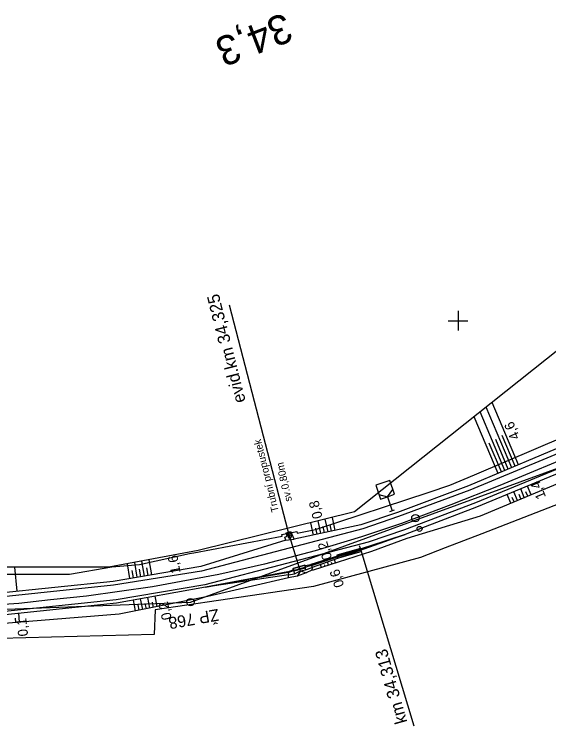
# Model space of a CAD drawing. Extents: x -805730 to -804640, y -1150889 to -1150366.
# Drawn here: x -805190.1 to -805081.6, y -1150682.3 to -1150537.8 of the extents above; entities that cross this region are included whole.
import ezdxf

# ---------------------------------------------------------------- set-up
doc = ezdxf.new("R2010")
doc.units = 0
for name, color, linetype in [('0381KM032-037P - Vrstva 1', 7, 'Continuous'), ('0381KM032-037P - Vrstva 13', 7, 'Continuous'), ('0381KM032-037P - Vrstva 17', 7, 'Continuous'), ('0381KM032-037P - Vrstva 19', 7, 'Continuous'), ('0381KM032-037P - Vrstva 4', 7, 'Continuous'), ('0381KM032-037P - Vrstva 48', 7, 'Continuous'), ('0381KM032-037P - Vrstva 49', 7, 'Continuous'), ('0381KM032-037P - Vrstva 7', 7, 'Continuous'), ('0381KM032-037P - Vrstva 9', 7, 'Continuous'), ('hran DP - hran DP', 7, 'Continuous'), ('krizky_1000 - Vrstva 1', 7, 'Continuous'), ('vyt_sit - polygon', 7, 'Continuous'), ('vyt_sit - stávající', 7, 'Continuous')]:
    doc.layers.add(name, color=color, linetype=linetype)

msp = doc.modelspace()

# ---------------------------------------------------------------- linework, layer by layer
at = {"layer": '0381KM032-037P - Vrstva 1'}
for points in [[(-805074.24, -1150626.27), (-805091.51, -1150633.48)], [(-805091.51, -1150633.48), (-805101.49, -1150637.38), (-805111.46, -1150641.17)], [(-805111.46, -1150641.17), (-805119.63, -1150643.91), (-805129.05, -1150646.75), (-805139.28, -1150649.43), (-805148.59, -1150651.52), (-805162.04, -1150654.03), (-805175.42, -1150655.94), (-805182.79, -1150656.72)], [(-805182.79, -1150656.72), (-805189.2, -1150657.4), (-805199.42, -1150658.12), (-805222.35, -1150659), (-805235.71, -1150659.34), (-805248.65, -1150659.92), (-805262.34, -1150660.99)]]:
    msp.add_lwpolyline(points, dxfattribs=at)
at = {"layer": '0381KM032-037P - Vrstva 13'}
for p, q in [((-805129.78, -1150649.7), (-805129.65, -1150650.12)), ((-805133.42, -1150650.74), (-805132.59, -1150650.52)), ((-805133.42, -1150650.74), (-805133.23, -1150651.44)), ((-805131.99, -1150650.77), (-805132.69, -1150651.85)), ((-805131.99, -1150650.77), (-805132.2, -1150650.41)), ((-805131.99, -1150650.77), (-805130.88, -1150651.21)), ((-805131, -1150650.07), (-805131.81, -1150650.3)), ((-805130.99, -1150650.58), (-805131, -1150650.07))]:
    msp.add_line(p, q, dxfattribs=at)
for points in [[(-805129.89, -1150649.51), (-805129.78, -1150649.7), (-805131, -1150650.07), (-805131, -1150650.07), (-805131.07, -1150649.74), (-805129.89, -1150649.51)], [(-805134.49, -1150651.14), (-805134.56, -1150650.98), (-805133.46, -1150650.58), (-805133.42, -1150650.74), (-805133.42, -1150650.74), (-805134.49, -1150651.14), (-805134.45, -1150651.61)], [(-805129.65, -1150650.12), (-805129.71, -1150650.67), (-805130.88, -1150651.21), (-805132.69, -1150651.85), (-805134.43, -1150652.2), (-805134.45, -1150651.61), (-805133.23, -1150651.44)], [(-805133.23, -1150651.44), (-805131.99, -1150650.77), (-805130.99, -1150650.58)], [(-805130.99, -1150650.58), (-805129.65, -1150650.12)]]:
    msp.add_lwpolyline(points, dxfattribs=at)
msp.add_ellipse((-805132.2, -1150650.41), major_axis=(-0.388, -0.106), ratio=0.004829, start_param=3.14712, end_param=6.275171, dxfattribs=at)
at = {"layer": '0381KM032-037P - Vrstva 17'}
msp.add_lwpolyline([(-805070.8, -1150598.9), (-805121.06, -1150638.84), (-805152.76, -1150646.7), (-805170.92, -1150650.08), (-805194.39, -1150650.05), (-805213.2, -1150651.26), (-805221.79, -1150652.33), (-805228.79, -1150654.03)], dxfattribs=at)
at = {"layer": '0381KM032-037P - Vrstva 19'}
for p, q in [((-805146.46, -1150596.75), (-805134.12, -1150644.47)), ((-805133.42, -1150650.74), (-805132.59, -1150650.52)), ((-805133.42, -1150650.74), (-805133.42, -1150650.74)), ((-805133.38, -1150650.83), (-805130.98, -1150650.17)), ((-805133.38, -1150650.83), (-805130.98, -1150650.17)), ((-805131.81, -1150650.3), (-805131, -1150650.07))]:
    msp.add_line(p, q, dxfattribs=at)
for points in [[(-805134.98, -1150644.55), (-805135.16, -1150643.96), (-805134.72, -1150643.76), (-805134.94, -1150643.05), (-805134.71, -1150643.05), (-805134.48, -1150643.83)], [(-805134.98, -1150644.55), (-805133.26, -1150644.39), (-805133.87, -1150642.97), (-805134.1, -1150642.94), (-805133.82, -1150643.72)], [(-805134.1, -1150642.94), (-805134.37, -1150642.96), (-805134.71, -1150643.05)], [(-805134.37, -1150642.96), (-805134.35, -1150643.15), (-805134.27, -1150643.62), (-805132.2, -1150650.41)], [(-805133.52, -1150650.35), (-805133.38, -1150650.83), (-805133.38, -1150650.83), (-805133.42, -1150650.74), (-805131, -1150650.07), (-805130.98, -1150650.17), (-805130.98, -1150650.17), (-805131.11, -1150649.68), (-805133.52, -1150650.35)], [(-805131.11, -1150649.68), (-805131.11, -1150649.68), (-805131.07, -1150649.74), (-805131, -1150650.07), (-805131, -1150650.07)], [(-805133.52, -1150650.35), (-805133.52, -1150650.35), (-805133.46, -1150650.58), (-805133.42, -1150650.74)]]:
    msp.add_lwpolyline(points, dxfattribs=at)
for centre, major_axis, ratio, start_param, end_param in [((-805134.15, -1150643.86), (0.331, 0.133), 0.755735, 2.535553, 6.304808), ((-805134.15, -1150643.86), (0.331, 0.133), 0.755735, 0.021623, 2.535553), ((-805132.2, -1150650.41), (0.388, 0.106), 0.004829, 1.569477, 6.288713), ((-805132.2, -1150650.41), (-0.388, -0.106), 0.004829, 3.14712, 4.71107)]:
    msp.add_ellipse(centre, major_axis=major_axis, ratio=ratio, start_param=start_param, end_param=end_param, dxfattribs=at)
at = {"layer": '0381KM032-037P - Vrstva 4'}
for points in [[(-804872.17, -1150539.66), (-804893.72, -1150547.52), (-804911.96, -1150555), (-804952.93, -1150572.63), (-804995.29, -1150590.69), (-805039.86, -1150609.18), (-805057.83, -1150616.69), (-805068.36, -1150621.07), (-805097.92, -1150633.57)], [(-804864.42, -1150538.53), (-804893.06, -1150548.77), (-804911.6, -1150556.2), (-804952.82, -1150573.68), (-804994.86, -1150591.44), (-805039.39, -1150610.13), (-805056.71, -1150617.44), (-805097.6, -1150634.39)], [(-804862.73, -1150542.41), (-804863.39, -1150541.46), (-804892.29, -1150551.48), (-804910.22, -1150558.86), (-804951.61, -1150576.23), (-804993.7, -1150593.96), (-805038.63, -1150612.92), (-805049.62, -1150617.53), (-805055.59, -1150619.94), (-805066.74, -1150624.75), (-805096.44, -1150637.01)], [(-804864.94, -1150543.15), (-804869.59, -1150544.8), (-804891.93, -1150552.26), (-804909.8, -1150559.87), (-804951.24, -1150577.2), (-804993.38, -1150594.6), (-805038.39, -1150613.8), (-805059.54, -1150622.79), (-805066.49, -1150625.57), (-805096.25, -1150637.87)], [(-805097.92, -1150633.57), (-805112.32, -1150638.96), (-805119.74, -1150641.46), (-805133.26, -1150644.39)], [(-805097.6, -1150634.39), (-805112.1, -1150639.75), (-805119.36, -1150642.27), (-805152.08, -1150650.89), (-805169.94, -1150653.7), (-805193.71, -1150656.24), (-805212.28, -1150657.22)], [(-805096.44, -1150637.01), (-805110.9, -1150642.46), (-805118.26, -1150644.98), (-805151.42, -1150653.61), (-805169.41, -1150656.67), (-805193.4, -1150659.17), (-805212.01, -1150660.08)], [(-805096.25, -1150637.87), (-805110.77, -1150643.45), (-805117.97, -1150645.76), (-805129.89, -1150649.51)], [(-805134.98, -1150644.55), (-805152.23, -1150649.93), (-805170.06, -1150652.94), (-805193.76, -1150655.4), (-805212.2, -1150656.84), (-805228.99, -1150656.61)], [(-805134.56, -1150650.98), (-805151.31, -1150654.12), (-805169.36, -1150657.36), (-805193.31, -1150659.84), (-805211.96, -1150660.88), (-805220.23, -1150661.07)]]:
    msp.add_lwpolyline(points, dxfattribs=at)
at = {"layer": '0381KM032-037P - Vrstva 48'}
for p, q in [((-805089.11, -1150629.85), (-805094.3, -1150617.57)), ((-805087.73, -1150629.26), (-805093.08, -1150616.6)), ((-805090.49, -1150630.43), (-805095.52, -1150618.54)), ((-805091.87, -1150631.02), (-805096.74, -1150619.51)), ((-805088.42, -1150629.55), (-805091.05, -1150623.32)), ((-805091.18, -1150630.72), (-805093.66, -1150624.87)), ((-805089.8, -1150630.14), (-805092.35, -1150624.1)), ((-805085.16, -1150635.34), (-805085.89, -1150633.59)), ((-805087.93, -1150636.49), (-805088.67, -1150634.73)), ((-805086.55, -1150635.91), (-805087.28, -1150634.16)), ((-805085.85, -1150635.62), (-805086.22, -1150634.75)), ((-805089.32, -1150637.07), (-805090.05, -1150635.3)), ((-805088.62, -1150636.78), (-805088.99, -1150635.9)), ((-805087.24, -1150636.2), (-805087.61, -1150635.32)), ((-805129.34, -1150643.54), (-805129.89, -1150641.03)), ((-805127.87, -1150643.22), (-805128.43, -1150640.67)), ((-805126.41, -1150642.91), (-805126.97, -1150640.3)), ((-805124.94, -1150642.59), (-805125.52, -1150639.94)), ((-805128.61, -1150643.38), (-805128.88, -1150642.11)), ((-805127.14, -1150643.06), (-805127.42, -1150641.78)), ((-805125.68, -1150642.75), (-805125.96, -1150641.44)), ((-805125.89, -1150648.25), (-805125.84, -1150648.39)), ((-805166.64, -1150652.36), (-805167.14, -1150649.38)), ((-805165.16, -1150652.11), (-805165.66, -1150649.1)), ((-805163.68, -1150651.86), (-805164.19, -1150648.83)), ((-805162.2, -1150651.61), (-805162.71, -1150648.55)), ((-805128.75, -1150649.15), (-805128.69, -1150649.34)), ((-805128.03, -1150648.93), (-805128.01, -1150649.01)), ((-805127.72, -1150650.11), (-805127.92, -1150649.5)), ((-805127.32, -1150648.7), (-805127.27, -1150648.86)), ((-805127.01, -1150649.88), (-805127.11, -1150649.57)), ((-805126.6, -1150648.48), (-805126.58, -1150648.55)), ((-805126.29, -1150649.66), (-805126.5, -1150649)), ((-805125.58, -1150649.43), (-805125.69, -1150649.09)), ((-805124.86, -1150649.2), (-805125.09, -1150648.51)), ((-805189.5, -1150654.96), (-805190.01, -1150650.05)), ((-805165.9, -1150652.24), (-805166.15, -1150650.74)), ((-805164.42, -1150651.99), (-805164.67, -1150650.48)), ((-805162.94, -1150651.74), (-805163.19, -1150650.22)), ((-805165.5, -1150658.95), (-805165.94, -1150656.75)), ((-805164.03, -1150658.66), (-805164.46, -1150656.48)), ((-805162.56, -1150658.36), (-805162.99, -1150656.22)), ((-805161.09, -1150658.07), (-805161.51, -1150655.95)), ((-805164.77, -1150658.8), (-805164.98, -1150657.71)), ((-805163.3, -1150658.51), (-805163.51, -1150657.43)), ((-805161.82, -1150658.22), (-805162.04, -1150657.15)), ((-805189.06, -1150661.23), (-805189.2, -1150659.41)), ((-805189.8, -1150661.29), (-805189.88, -1150660.39))]:
    msp.add_line(p, q, dxfattribs=at)
at = {"layer": '0381KM032-037P - Vrstva 49'}
for p, q in [((-805134.98, -1150644.55), (-805133.26, -1150644.39)), ((-805129.78, -1150649.7), (-805117.97, -1150645.76)), ((-805134.49, -1150651.14), (-805151.31, -1150654.12)), ((-805134.45, -1150651.61), (-805151.31, -1150654.12))]:
    msp.add_line(p, q, dxfattribs=at)
for points in [[(-804871.36, -1150538.86), (-804872.17, -1150539.66), (-804893.72, -1150547.52), (-804911.96, -1150555), (-804952.93, -1150572.63), (-804995.29, -1150590.69), (-805039.86, -1150609.18), (-805057.83, -1150616.69), (-805068.36, -1150621.07), (-805097.92, -1150633.57)], [(-804909.8, -1150559.87), (-804951.24, -1150577.2), (-804993.38, -1150594.6), (-805038.39, -1150613.8), (-805050.01, -1150619.25), (-805055.21, -1150621.51), (-805059.54, -1150622.79), (-805066.49, -1150625.57), (-805096.25, -1150637.87)], [(-805070.8, -1150598.9), (-805121.06, -1150638.84), (-805152.76, -1150646.7), (-805170.92, -1150650.08), (-805194.39, -1150650.05), (-805213.2, -1150651.26), (-805221.79, -1150652.33), (-805228.79, -1150654.03)], [(-805065.73, -1150627.22), (-805095.53, -1150639.67)], [(-805097.92, -1150633.57), (-805112.32, -1150638.96), (-805119.74, -1150641.46), (-805133.26, -1150644.39)], [(-805096.25, -1150637.87), (-805110.77, -1150643.45), (-805129.65, -1150650.12)], [(-805095.53, -1150639.67), (-805110.42, -1150644.21), (-805117.6, -1150646.87), (-805129.42, -1150650.66)], [(-805129.89, -1150649.51), (-805117.97, -1150645.76), (-805110.77, -1150643.45)], [(-805134.98, -1150644.55), (-805152.23, -1150649.93), (-805170.06, -1150652.94), (-805193.76, -1150655.4), (-805212.2, -1150656.84), (-805221.82, -1150655.55)], [(-805151.31, -1150654.12), (-805134.56, -1150650.98), (-805133.46, -1150650.58), (-805133.52, -1150650.35), (-805133.52, -1150650.35), (-805131.11, -1150649.68), (-805131.11, -1150649.68), (-805131.07, -1150649.74), (-805129.89, -1150649.51)], [(-805129.78, -1150649.7), (-805131, -1150650.07), (-805131.81, -1150650.3)], [(-805134.49, -1150651.14), (-805133.42, -1150650.74), (-805132.59, -1150650.52)], [(-805134.45, -1150651.61), (-805133.23, -1150651.44), (-805131.99, -1150650.77), (-805130.99, -1150650.58), (-805129.65, -1150650.12)], [(-805129.42, -1150650.66), (-805129.71, -1150650.67), (-805130.88, -1150651.21), (-805132.69, -1150651.85), (-805134.43, -1150652.2)], [(-805134.43, -1150652.2), (-805150.83, -1150656.03), (-805168.82, -1150659.61), (-805193.05, -1150661.55), (-805211.83, -1150662.42), (-805220.04, -1150663.05)], [(-805151.31, -1150654.12), (-805169.36, -1150657.36), (-805193.31, -1150659.84), (-805211.96, -1150660.88), (-805220.13, -1150661.62)]]:
    msp.add_lwpolyline(points, dxfattribs=at)
msp.add_ellipse((-805132.2, -1150650.41), major_axis=(0.388, 0.106), ratio=0.004829, start_param=0.005528, end_param=3.133579, dxfattribs=at)
at = {"layer": '0381KM032-037P - Vrstva 7'}
for p, q in [((-805114.33, -1150635.74), (-805113.38, -1150638.58)), ((-805113.85, -1150638.74), (-805112.9, -1150638.42)), ((-805107.87, -1150642.28), (-805107.77, -1150642.28))]:
    msp.add_line(p, q, dxfattribs=at)
for points in [[(-805114.33, -1150635.74), (-805112.91, -1150635.26), (-805113.86, -1150632.42), (-805116.71, -1150633.37), (-805115.75, -1150636.22), (-805114.33, -1150635.74)], [(-805116.07, -1150635.27), (-805114.33, -1150635.74), (-805113.23, -1150634.31)]]:
    msp.add_lwpolyline(points, dxfattribs=at)
for centre, radius in [((-805108.67, -1150640.09), 0.75), ((-805107.82, -1150642.28), 0.5)]:
    msp.add_circle(centre, radius, dxfattribs=at)
at = {"layer": '0381KM032-037P - Vrstva 9'}
for p, q in [((-805119.84, -1150646.28), (-805124.65, -1150647.63)), ((-805119.84, -1150646.28), (-805120, -1150645.7)), ((-805119.68, -1150646.86), (-805119.84, -1150646.28)), ((-805119.76, -1150646.57), (-805109, -1150682.26)), ((-805124.65, -1150647.63), (-805124.49, -1150648.21)), ((-805124.49, -1150648.21), (-805119.68, -1150646.86))]:
    msp.add_line(p, q, dxfattribs=at)
at = {"layer": 'hran DP - hran DP'}
for p, q in [((-805096.7, -1150631.27), (-805066.7, -1150618.51)), ((-805101.66, -1150633.38), (-805096.7, -1150631.27)), ((-805105.89, -1150634.79), (-805101.66, -1150633.38)), ((-805128.92, -1150642.38), (-805105.89, -1150634.79)), ((-805077.33, -1150636.32), (-805095.21, -1150643.26)), ((-805132.67, -1150643.17), (-805128.92, -1150642.38)), ((-805153.67, -1150647.14), (-805135.75, -1150643.74)), ((-805135.82, -1150643.41), (-805132.75, -1150642.8)), ((-805135.75, -1150643.74), (-805135.82, -1150643.41)), ((-805132.75, -1150642.8), (-805132.67, -1150643.17)), ((-805095.21, -1150643.26), (-805102.65, -1150646.15)), ((-805102.65, -1150646.15), (-805107.63, -1150648.08)), ((-805164.69, -1150649.54), (-805154.57, -1150647.29)), ((-805154.57, -1150647.29), (-805153.67, -1150647.14)), ((-805107.63, -1150648.08), (-805129.38, -1150653.98)), ((-805170.32, -1150649.99), (-805164.69, -1150649.54)), ((-805178.93, -1150651.45), (-805170.32, -1150649.99)), ((-805208.17, -1150651.53), (-805178.93, -1150651.45)), ((-805129.38, -1150653.98), (-805161.49, -1150658.69)), ((-805161.49, -1150658.69), (-805161.69, -1150663.73)), ((-805161.69, -1150663.73), (-805193.03, -1150664.54))]:
    msp.add_line(p, q, dxfattribs=at)
at = {"layer": 'krizky_1000 - Vrstva 1'}
for points in [[(-805100, -1150598), (-805100, -1150602)], [(-805102, -1150600), (-805098, -1150600)]]:
    msp.add_lwpolyline(points, dxfattribs=at)
at = {"layer": 'vyt_sit - polygon'}
for p, q in [((-805154.33, -1150657.15), (-805047.55, -1150618.19)), ((-805292.36, -1150662.43), (-805154.33, -1150657.15))]:
    msp.add_line(p, q, dxfattribs=at)
at = {"layer": 'vyt_sit - stávající'}
msp.add_line((-805154.38, -1150657.15), (-805154.28, -1150657.15), dxfattribs=at)
msp.add_circle((-805154.33, -1150657.15), 0.756, dxfattribs=at)

# ---------------------------------------------------------------- texts
at = {"layer": '0381KM032-037P - Vrstva 19'}
for s, height, rotation, p in [('evid.km 34,325', 2.5, 104.0597, (-805143.1, -1150616.37)), ('Trubní propustek', 1.5, 104.0315, (-805136.39, -1150638.68)), ('sv.0,80m', 1.5, 102.6099, (-805133.72, -1150636.58))]:
    msp.add_text(s, height=height, rotation=rotation, dxfattribs=at).set_placement(p)
at = {"layer": '0381KM032-037P - Vrstva 48'}
for s, rotation, p in [('4,6', 113.4709, (-805087.41, -1150623.69)), ('1,4', 112.4607, (-805082.11, -1150635.78)), ('0,8', 103.9362, (-805127.51, -1150639.96)), ('0,2', 106.8529, (-805125.55, -1150648.25)), ('1,6', 100.857, (-805156.33, -1150651.13)), ('0,6', 107.7953, (-805123.1, -1150653.81)), ('0,2', 103.235, (-805158.12, -1150660.52)), ('0,1', 95.8989, (-805187.31, -1150664))]:
    msp.add_text(s, height=2, rotation=rotation, dxfattribs=at).set_placement(p)
at = {"layer": '0381KM032-037P - Vrstva 7'}
msp.add_text('34,3', height=6, rotation=201.0798, dxfattribs=at).set_placement((-805135.2, -1150537.34))
at = {"layer": '0381KM032-037P - Vrstva 9'}
msp.add_text('km 34,313', height=2.5, rotation=105.6206, dxfattribs=at).set_placement((-805110.3, -1150681.5))
at = {"layer": 'vyt_sit - stávající'}
msp.add_text('ŽP 768', height=2.4, rotation=190, dxfattribs=at).set_placement((-805148.77, -1150658.51))

doc.saveas('drawing.dxf')
